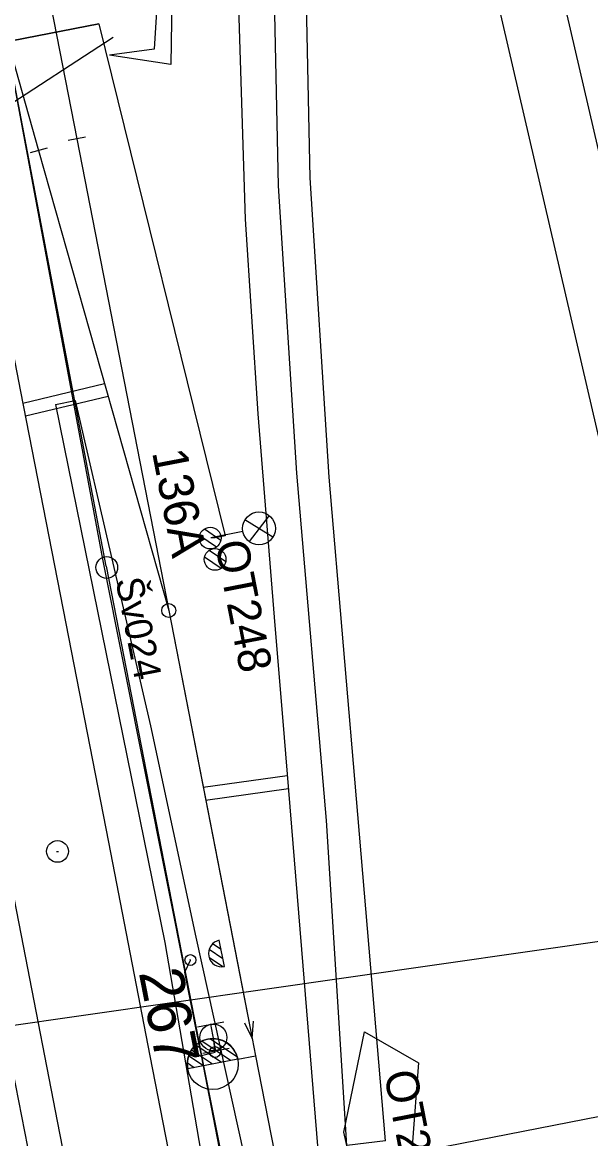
# Model space of a CAD drawing. Extents: x -545846 to -545044, y -1122650 to -1119108.
# Drawn here: x -545663.1 to -545637, y -1119489.2 to -1119438 of the extents above; entities that cross this region are included whole.
import ezdxf

# ---------------------------------------------------------------- set-up
doc = ezdxf.new("R2010")
doc.units = 0
for name, color, linetype in [('osvětlené plochy-hodnota-obrys', 7, 'Continuous'), ('Vrstva 1 - Koleje', 7, 'Continuous'), ('Vrstva 11 - Trakce', 7, 'Continuous'), ('Vrstva 2 - Vyhybky', 7, 'Continuous'), ('Vrstva 25', 7, 'Continuous'), ('Vrstva 26', 7, 'Continuous'), ('Vrstva 27', 7, 'Continuous'), ('Vrstva 28 - zabzar', 7, 'Continuous'), ('Vrstva 3 - Lisy - Pocitaci body', 7, 'Continuous'), ('Vrstva 4 - Teren - stezky - prechody - plochy', 7, 'Continuous'), ('Vrstva 43', 7, 'Continuous'), ('Vrstva 44', 7, 'Continuous'), ('Vrstva 51', 7, 'Continuous'), ('Vrstva 63', 7, 'Continuous'), ('Vrstva 7 - Namezniky-vystroj', 7, 'Continuous')]:
    doc.layers.add(name, color=color, linetype=linetype)

msp = doc.modelspace()

# ---------------------------------------------------------------- linework, layer by layer
at = {"layer": 'osvětlené plochy-hodnota-obrys'}
for points in [[(-545716.386, -1119223.717), (-545705.994, -1119221.66), (-545669.439, -1119408.759), (-545659.4, -1119462.635), (-545647.69, -1119521.347), (-545640.519, -1119558.729), (-545633.585, -1119589.698), (-545629.517, -1119613.814), (-545623.042, -1119645.057), (-545619.034, -1119667.556), (-545607.519, -1119727.517)], [(-545609.939, -1119482.977), (-545646.431, -1119490.114), (-545644.897, -1119509.516)]]:
    msp.add_lwpolyline(points, dxfattribs=at)
at = {"layer": 'Vrstva 1 - Koleje'}
for points in [[(-545653.043, -1119323.451), (-545650.994, -1119334.109), (-545649.296, -1119347.452), (-545648.631, -1119357.273), (-545648.467, -1119367.291), (-545648.846, -1119377.553), (-545649.716, -1119387.269), (-545651.731, -1119405.227), (-545652.454, -1119413.336), (-545653.029, -1119424.1), (-545653.062, -1119427.38), (-545653.109, -1119432.084), (-545653.161, -1119437.325), (-545652.856, -1119447.037), (-545652.275, -1119455.964), (-545651.518, -1119465.287), (-545651.062, -1119470.807), (-545650.206, -1119481.273), (-545649.41, -1119491.02), (-545648.05, -1119507.574), (-545645.027, -1119523.098), (-545644.874, -1119523.883)], [(-545681.637, -1119335.101), (-545671.298, -1119388.278), (-545670.76, -1119391.045), (-545670.414, -1119392.823), (-545669.934, -1119395.293), (-545667.967, -1119405.429), (-545666.055, -1119415.218), (-545664.157, -1119424.959), (-545662.28, -1119434.594), (-545660.571, -1119443.365), (-545656.357, -1119464.982), (-545653.314, -1119480.588), (-545652.53, -1119484.609), (-545652.377, -1119485.394)], [(-545683.274, -1119376.56), (-545681.242, -1119386.97), (-545679.47, -1119396.069), (-545677.244, -1119407.477), (-545675.184, -1119418.032), (-545673.045, -1119429.027), (-545670.931, -1119439.856), (-545669.293, -1119448.281), (-545667.274, -1119458.644), (-545665.203, -1119469.256), (-545663.032, -1119480.361), (-545661.358, -1119488.941), (-545659.379, -1119499.086)], [(-545675.912, -1119389.513), (-545675.759, -1119390.298), (-545671.927, -1119409.919), (-545665.915, -1119431.178), (-545662.323, -1119443.901), (-545656.357, -1119464.982), (-545652.53, -1119484.609), (-545652.377, -1119485.394)], [(-545675.912, -1119389.513), (-545675.759, -1119390.298), (-545674.983, -1119394.269), (-545671.927, -1119409.919), (-545667.706, -1119431.538), (-545665.572, -1119442.504), (-545664.599, -1119447.508), (-545663.149, -1119454.944), (-545661.077, -1119465.581), (-545659.119, -1119475.61), (-545657.219, -1119485.395), (-545655.182, -1119495.829), (-545653.541, -1119504.242), (-545653.037, -1119506.841)], [(-545652.377, -1119485.394), (-545651.228, -1119491.26), (-545648.05, -1119507.574), (-545645.027, -1119523.098), (-545644.874, -1119523.883)]]:
    msp.add_lwpolyline(points, dxfattribs=at)
at = {"layer": 'Vrstva 11 - Trakce'}
for p, q in [((-545654.719, -1119461.246), (-545653.962, -1119461.759)), ((-545654.935, -1119461.552), (-545654.168, -1119462.072)), ((-545654.499, -1119462.224), (-545653.742, -1119462.737)), ((-545654.715, -1119462.53), (-545653.948, -1119463.05))]:
    msp.add_line(p, q, dxfattribs=at)
for centre in [(-545654.451, -1119461.664), (-545654.231, -1119462.642)]:
    msp.add_circle(centre, 0.5, dxfattribs=at)
at = {"layer": 'Vrstva 2 - Vyhybky'}
for p, q in [((-545660.178, -1119443.289), (-545660.964, -1119443.441)), ((-545661.938, -1119443.792), (-545662.708, -1119444.01)), ((-545653.518, -1119485.619), (-545654.844, -1119484.726)), ((-545653.208, -1119485.466), (-545654.468, -1119484.617)), ((-545654.351, -1119485.781), (-545655.31, -1119485.135)), ((-545653.934, -1119485.7), (-545655.113, -1119484.906)), ((-545655.185, -1119485.943), (-545655.501, -1119485.73)), ((-545653.185, -1119485.554), (-545655.483, -1119486.001)), ((-545654.768, -1119485.862), (-545655.441, -1119485.408)), ((-545653.185, -1119485.553), (-545653.185, -1119485.554)), ((-545653.184, -1119485.554), (-545652.377, -1119485.394))]:
    msp.add_line(p, q, dxfattribs=at)
for points in [[(-545660.571, -1119443.365), (-545656.357, -1119464.982), (-545652.53, -1119484.609), (-545652.377, -1119485.394)], [(-545662.323, -1119443.901), (-545656.357, -1119464.982)], [(-545652.881, -1119483.89), (-545652.53, -1119484.609), (-545652.475, -1119483.811)]]:
    msp.add_lwpolyline(points, dxfattribs=at)
for centre, radius in [((-545656.357, -1119464.982), 0.32), ((-545654.34, -1119485.778), 1.17)]:
    msp.add_circle(centre, radius, dxfattribs=at)
msp.add_arc((-545654.334, -1119485.778), 1.171, 11.0562, 191.017, dxfattribs=at)
at = {"layer": 'Vrstva 25'}
for p, q in [((-545651.757, -1119460.624), (-545652.67, -1119461.823)), ((-545651.578, -1119461.623), (-545652.862, -1119460.831)), ((-545652.957, -1119461.363), (-545654.429, -1119461.65))]:
    msp.add_line(p, q, dxfattribs=at)
msp.add_circle((-545652.216, -1119461.221), 0.754, dxfattribs=at)
at = {"layer": 'Vrstva 26'}
for points in [[(-545675.368, -1119441.242), (-545674.422, -1119440.976), (-545659.563, -1119438.09), (-545653.772, -1119461.566), (-545654.229, -1119461.646), (-545654.429, -1119461.65)], [(-545659.563, -1119438.09), (-545674.422, -1119440.976)]]:
    msp.add_lwpolyline(points, dxfattribs=at)
at = {"layer": 'Vrstva 27'}
for p, q in [((-545655.355, -1119481.035), (-545655.365, -1119480.985)), ((-545654.225, -1119485.255), (-545654.235, -1119485.205))]:
    msp.add_line(p, q, dxfattribs=at)
for centre in [(-545655.36, -1119481.01), (-545654.23, -1119485.23)]:
    msp.add_circle(centre, 0.25, dxfattribs=at)
at = {"layer": 'Vrstva 28 - zabzar'}
for points in [[(-545651.64, -1119501.97), (-545654.86, -1119485.39), (-545655.07, -1119484.34), (-545655.62, -1119481.57), (-545655.36, -1119481.01)], [(-545654.86, -1119485.39), (-545654.23, -1119485.23), (-545654.31, -1119484.56)]]:
    msp.add_lwpolyline(points, dxfattribs=at)
at = {"layer": 'Vrstva 3 - Lisy - Pocitaci body'}
for p, q in [((-545653.797, -1119481.311), (-545654.041, -1119480.104)), ((-545654.041, -1119480.104), (-545654.041, -1119480.104)), ((-545653.869, -1119480.956), (-545654.507, -1119480.532)), ((-545653.955, -1119480.528), (-545654.351, -1119480.269)), ((-545653.88, -1119481.322), (-545654.492, -1119480.914)), ((-545655.032, -1119484.073), (-545653.823, -1119483.838)), ((-545654.192, -1119485.165), (-545654.428, -1119483.955)), ((-545654.797, -1119485.282), (-545653.588, -1119485.047))]:
    msp.add_line(p, q, dxfattribs=at)
msp.add_circle((-545654.311, -1119484.558), 0.616, dxfattribs=at)
for start, end in [(101.411, 191.411), (191.411, 281.411)]:
    msp.add_arc((-545653.919, -1119480.708), 0.616, start, end, dxfattribs=at)
at = {"layer": 'Vrstva 4 - Teren - stezky - prechody - plochy'}
for points in [[(-545663.732, -1119493.482), (-545662.217, -1119493.136), (-545662.27, -1119492.38), (-545664.76, -1119479.724), (-545673.059, -1119437.391), (-545683.638, -1119382.878), (-545688.896, -1119355.974), (-545694.44, -1119327.554), (-545697.827, -1119310.185), (-545704.93, -1119274.138), (-545706.059, -1119274.463)], [(-545648.192, -1119489.509), (-545649.123, -1119474.606), (-545650.474, -1119458.681), (-545651.316, -1119445.516), (-545651.575, -1119433.32), (-545651.457, -1119423.888), (-545651.028, -1119417.952), (-545652.093, -1119417.118), (-545653.369, -1119416.995), (-545654.136, -1119414.919), (-545655.802, -1119414.917), (-545656.275, -1119430.136), (-545656.44, -1119429.936), (-545657.018, -1119439.251), (-545659.066, -1119439.528)], [(-545646.422, -1119489.304), (-545648.192, -1119489.509), (-545649.123, -1119474.606), (-545650.474, -1119458.681), (-545651.316, -1119445.516), (-545651.575, -1119433.32), (-545651.457, -1119423.888), (-545651.028, -1119417.952)], [(-545646.422, -1119489.304), (-545647.676, -1119474.337), (-545648.998, -1119458.864), (-545649.869, -1119445.15), (-545650.093, -1119434.206), (-545649.945, -1119423.894), (-545649.917, -1119418.955), (-545651.028, -1119417.952)], [(-545656.275, -1119430.136), (-545656.099, -1119430.029), (-545656.259, -1119439.96), (-545659.066, -1119439.528)], [(-545661.554, -1119455.534), (-545660.643, -1119455.361), (-545657.192, -1119470.267), (-545655.109, -1119479.957), (-545652.91, -1119489.92)], [(-545661.554, -1119455.534), (-545656.541, -1119480.207), (-545654.811, -1119490.256), (-545652.91, -1119489.92)]]:
    msp.add_lwpolyline(points, dxfattribs=at)
at = {"layer": 'Vrstva 43'}
msp.add_circle((-545659.199, -1119463.01), 0.5, dxfattribs=at)
at = {"layer": 'Vrstva 44'}
for points in [[(-545659.224, -1119462.954), (-545669.377, -1119409.578), (-545676.105, -1119375.826)], [(-545659.224, -1119462.954), (-545649.574, -1119512.455), (-545640.335, -1119560.272), (-545649.193, -1119561.882), (-545649.25, -1119561.916)]]:
    msp.add_lwpolyline(points, dxfattribs=at)
at = {"layer": 'Vrstva 51'}
for points in [[(-545654.713, -1119405.937), (-545655.51, -1119411.125), (-545652.928, -1119414), (-545647.829, -1119421.354), (-545641.977, -1119434.026), (-545634.094, -1119468.04), (-545630.811, -1119484.542), (-545628.493, -1119498.884), (-545628.199, -1119500.245), (-545627.599, -1119500.06), (-545616.366, -1119546.501)], [(-545654.713, -1119405.937), (-545651.834, -1119408.923), (-545645.293, -1119419.914), (-545639.142, -1119433.19), (-545631.2, -1119467.367), (-545627.715, -1119485.099), (-545624.675, -1119499.385), (-545613.784, -1119545.76)], [(-545639.337, -1119525.385), (-545641.443, -1119515.827), (-545644.606, -1119500.441), (-545645.692, -1119500.53), (-545648.327, -1119488.905), (-545647.376, -1119484.306), (-545644.897, -1119485.722), (-545645.185, -1119489.544), (-545644.321, -1119494.225), (-545642.597, -1119493.907), (-545640.807, -1119501.182), (-545642.366, -1119501.498), (-545641.978, -1119503.357)]]:
    msp.add_lwpolyline(points, dxfattribs=at)
at = {"layer": 'Vrstva 63'}
for p, q in [((-545658.91, -1119438.714), (-545708.862, -1119471.264)), ((-545614.243, -1119476.951), (-545705.196, -1119489.997))]:
    msp.add_line(p, q, dxfattribs=at)
at = {"layer": 'Vrstva 7 - Namezniky-vystroj'}
for p, q in [((-545663.045, -1119455.478), (-545659.299, -1119454.585)), ((-545662.93, -1119456.067), (-545659.136, -1119455.163)), ((-545654.777, -1119473.085), (-545650.919, -1119472.553)), ((-545654.662, -1119473.675), (-545650.87, -1119473.152)), ((-545661.507, -1119476.028), (-545661.407, -1119476.028))]:
    msp.add_line(p, q, dxfattribs=at)
msp.add_circle((-545661.457, -1119476.028), 0.5, dxfattribs=at)

# ---------------------------------------------------------------- texts
at = {"layer": 'Vrstva 11 - Trakce'}
msp.add_text('136A', height=1.6, rotation=280.86, dxfattribs=at).set_placement((-545657.125, -1119457.724))
at = {"layer": 'Vrstva 2 - Vyhybky'}
msp.add_text('267', height=2, rotation=281.0366, dxfattribs=at).set_placement((-545657.733, -1119481.575))
at = {"layer": 'Vrstva 25'}
for s, rotation, p in [('OT248', 281.0227, (-545654.235, -1119461.899)), ('OT245', 281.0233, (-545646.492, -1119486.197))]:
    msp.add_text(s, height=1.5, rotation=rotation, dxfattribs=at).set_placement(p)
at = {"layer": 'Vrstva 43'}
msp.add_text('Šv024', height=1.25, rotation=280.9998, dxfattribs=at).set_placement((-545658.801, -1119463.584))

doc.saveas('drawing.dxf')
